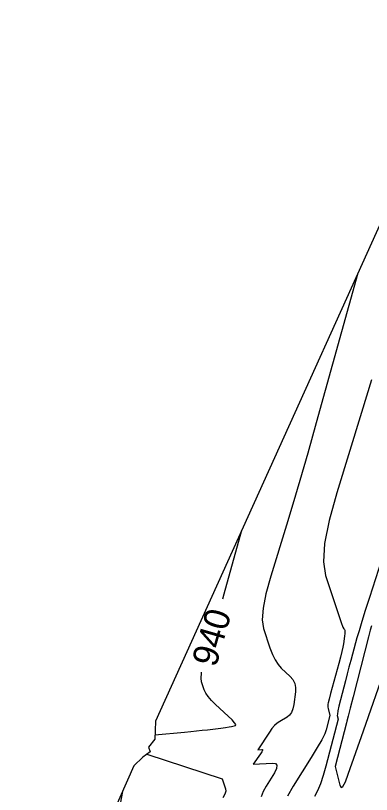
# Model space of a CAD drawing. Extents: x 2175772 to 2185556, y 721391 to 722853.
# Drawn here: x 2178632.3 to 2178671.4, y 721969.8 to 722055.4 of the extents above; entities that cross this region are included whole.
import ezdxf

# ---------------------------------------------------------------- set-up
doc = ezdxf.new("R2010")
doc.units = 0
for name, color, linetype in [('DT_X_Contour_Major', 7, 'Continuous'), ('DT_X_Contour_Minor', 7, 'Continuous'), ('DT_X_TIN_Hull', 7, 'Continuous')]:
    doc.layers.add(name, color=color, linetype=linetype)

msp = doc.modelspace()

# ---------------------------------------------------------------- linework, layer by layer
at = {"layer": 'DT_X_Contour_Major'}
for points in [[(2178655.046, 721991.36), (2178655.191, 721991.876), (2178657.145, 721998.881)], [(2178647.591, 721976.383), (2178650.846, 721976.692), (2178651.526, 721976.758), (2178652.171, 721976.825), (2178652.781, 721976.893), (2178653.357, 721976.961), (2178654.846, 721977.143), (2178655.347, 721977.207), (2178655.735, 721977.263), (2178656.009, 721977.31), (2178656.169, 721977.348), (2178656.446, 721977.438), (2178656.473, 721977.527), (2178656.346, 721977.726), (2178656.065, 721978.035), (2178655.63, 721978.454), (2178654.266, 721979.717), (2178653.804, 721980.174), (2178653.443, 721980.596), (2178653.181, 721980.983), (2178653.02, 721981.336), (2178652.723, 721982.23), (2178652.661, 721982.635), (2178652.695, 721983.181), (2178652.717, 721983.292)], [(2178646.689, 721974.256), (2178654.987, 721971.563), (2178655.356, 721970.477), (2178655.375, 721970.212), (2178655.273, 721969.882), (2178655.051, 721969.486)]]:
    msp.add_lwpolyline(points, dxfattribs=at)
at = {"layer": 'DT_X_Contour_Minor'}
for points in [[(2178669.91, 722027.129), (2178665.328, 722010.698), (2178664.387, 722007.354), (2178663.529, 722004.365), (2178662.753, 722001.731), (2178662.059, 721999.451), (2178660.32, 721993.846), (2178659.782, 721991.908), (2178659.472, 721990.299), (2178659.391, 721989.019), (2178659.538, 721988.068), (2178660.234, 721985.971), (2178660.508, 721985.24), (2178660.808, 721984.622), (2178661.133, 721984.116), (2178661.485, 721983.722), (2178662.458, 721982.821), (2178662.768, 721982.46), (2178662.969, 721982.054), (2178663.061, 721981.602), (2178663.044, 721981.104), (2178662.853, 721979.715), (2178662.753, 721979.238), (2178662.597, 721978.849), (2178662.384, 721978.546), (2178662.114, 721978.332), (2178661.32, 721977.876), (2178661.025, 721977.675), (2178660.737, 721977.412), (2178660.455, 721977.088), (2178660.18, 721976.703), (2178658.909, 721974.763), (2178659.343, 721974.8), (2178659.404, 721974.775), (2178659.398, 721974.687), (2178659.326, 721974.534), (2178659.189, 721974.317), (2178658.393, 721973.155), (2178660.502, 721973.285), (2178660.855, 721973.24), (2178661.008, 721973.05), (2178660.963, 721972.714), (2178660.719, 721972.233), (2178659.803, 721970.756), (2178659.495, 721970.183), (2178659.258, 721969.571)], [(2178671.412, 722015.408), (2178670.32, 722011.821), (2178667.583, 722002.999), (2178666.737, 721999.949), (2178666.249, 721997.417), (2178666.121, 721995.403), (2178666.352, 721993.907), (2178667.447, 721990.606), (2178667.812, 721989.518), (2178668.083, 721988.731), (2178668.261, 721988.245), (2178668.345, 721988.06), (2178668.447, 721987.965), (2178668.475, 721987.894), (2178668.483, 721987.753), (2178668.47, 721987.541), (2178668.436, 721987.258), (2178668.319, 721986.409), (2178668.254, 721986.034), (2178668.147, 721985.546), (2178667.997, 721984.945), (2178667.805, 721984.23), (2178666.896, 721980.941), (2178666.73, 721980.322), (2178666.623, 721979.905), (2178666.593, 721979.749), (2178666.585, 721979.592), (2178666.597, 721979.434), (2178666.631, 721979.276), (2178666.836, 721978.536), (2178666.423, 721976.961), (2178666.254, 721976.517), (2178665.922, 721975.861), (2178665.428, 721974.991), (2178664.771, 721973.908), (2178662.804, 721970.737), (2178662.153, 721969.639)], [(2178672.515, 721995.606), (2178671.182, 721991.489), (2178670.721, 721990.053), (2178670.338, 721988.835), (2178670.034, 721987.833), (2178669.807, 721987.048), (2178669.308, 721985.244), (2178669.119, 721984.554), (2178668.927, 721983.838), (2178668.731, 721983.095), (2178668.532, 721982.325), (2178667.996, 721980.237), (2178667.824, 721979.541), (2178667.707, 721979.021), (2178667.646, 721978.675), (2178667.641, 721978.505), (2178667.748, 721978.118), (2178666.394, 721972.948), (2178666.097, 721971.91), (2178665.788, 721971.012), (2178665.466, 721970.253), (2178665.132, 721969.634)], [(2178671.41, 721988.364), (2178671.264, 721987.894), (2178671.146, 721987.468), (2178671.062, 721987.152), (2178670.656, 721985.582), (2178669.37, 721980.568), (2178669.054, 721979.333), (2178668.828, 721978.449), (2178668.694, 721977.916), (2178668.651, 721977.733), (2178668.66, 721977.699), (2178667.407, 721972.916), (2178667.923, 721970.877), (2178668.065, 721970.623), (2178668.266, 721970.735), (2178668.529, 721971.213), (2178668.853, 721972.058), (2178670.506, 721976.853), (2178672.96, 721983.864)], [(2178644.01, 721970.151), (2178643.641, 721968.234)]]:
    msp.add_lwpolyline(points, dxfattribs=at)
at = {"layer": 'DT_X_TIN_Hull'}
msp.add_lwpolyline([(2178706.948, 722109.71), (2178684.501, 722059.417), (2178647.66, 721977.892), (2178647.62, 721976.886), (2178647.564, 721975.92), (2178646.889, 721975.04), (2178647.047, 721974.532), (2178646.259, 721973.924), (2178645.272, 721972.998), (2178625.76, 721928.988)], dxfattribs=at)

# ---------------------------------------------------------------- texts
at = {"layer": 'DT_X_Contour_Major'}
msp.add_text('940', height=2.8, rotation=73.89571, dxfattribs=at).set_placement((2178654.291, 721983.73))

doc.saveas('drawing.dxf')
